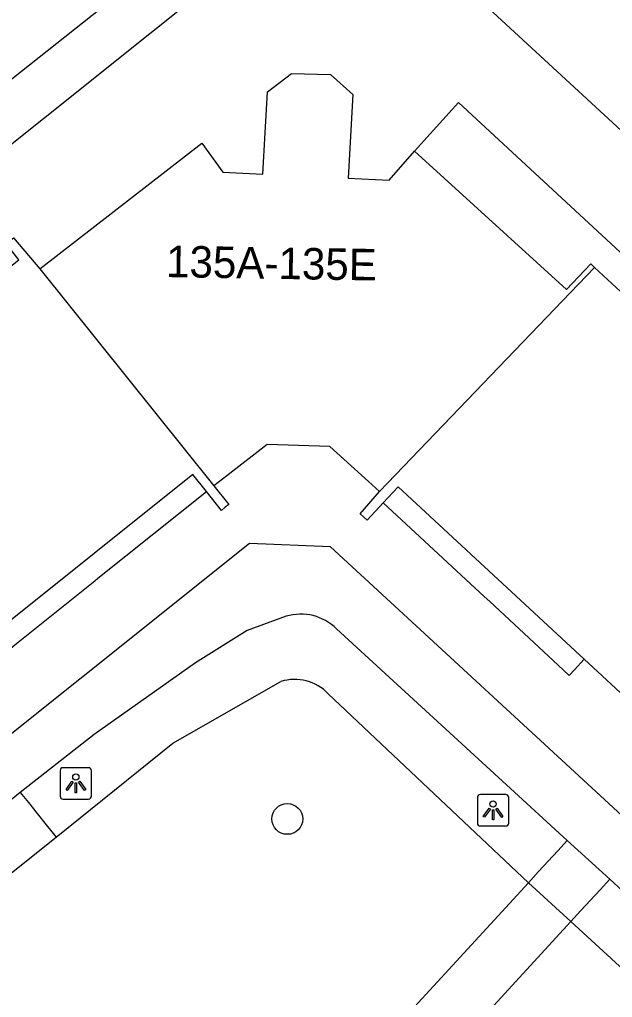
# Model space of a CAD drawing. Extents: x 159040 to 160094, y 381214 to 382518.
# Drawn here: x 159665.82 to 159684.64, y 381789.2 to 381820.24 of the extents above; entities that cross this region are included whole.
import ezdxf

# ---------------------------------------------------------------- set-up
doc = ezdxf.new("R2010")
doc.units = 0
for name, color, linetype in [('IMGEO_Boom', 7, 'Continuous'), ('IMGEO_Haag', 7, 'Continuous'), ('IMGEO_Lichtpunt', 7, 'Continuous'), ('IMGEO_Pand', 7, 'Continuous'), ('IMGEO_Pand_nummerreeks', 7, 'Continuous'), ('IMGEO_Pand_overbouw', 7, 'Continuous'), ('IMGEO_Rijbaan_lokaal_open', 7, 'Continuous'), ('IMGEO_Voetpad_gesloten', 7, 'Continuous'), ('IMGEO_Voetpad_open', 7, 'Continuous')]:
    doc.layers.add(name, color=color, linetype=linetype)

msp = doc.modelspace()

# ---------------------------------------------------------------- linework, layer by layer
at = {"layer": 'IMGEO_Boom'}
msp.add_circle((159674.317, 381794.866), 0.489, dxfattribs=at)
at = {"layer": 'IMGEO_Haag'}
for points in [[(159672.049, 381823.487), (159655.728, 381810.546)], [(159666.977, 381794.289), (159670.685, 381797.275), (159674.114, 381799.226)], [(159675.617, 381798.839), (159681.97, 381792.84)], [(159683.317, 381791.605), (159691.286, 381784.296)]]:
    msp.add_lwpolyline(points, dxfattribs=at)
msp.add_arc((159674.554, 381797.824), 1.47, 43.6887, 107.433, dxfattribs=at)
at = {"layer": 'IMGEO_Lichtpunt'}
for p, q in [((159667.108, 381796.396), (159667.108, 381795.589)), ((159667.108, 381796.396), (159667.108, 381795.589)), ((159668.01, 381796.491), (159667.202, 381796.491)), ((159668.01, 381796.491), (159667.202, 381796.491)), ((159668.104, 381795.589), (159668.104, 381796.396)), ((159668.104, 381795.589), (159668.104, 381796.396)), ((159667.202, 381795.495), (159668.01, 381795.495)), ((159667.202, 381795.495), (159668.01, 381795.495)), ((159680.351, 381795.543), (159680.351, 381794.736)), ((159680.351, 381795.543), (159680.351, 381794.736)), ((159681.253, 381795.638), (159680.445, 381795.638)), ((159681.253, 381795.638), (159680.445, 381795.638)), ((159681.347, 381794.736), (159681.347, 381795.543)), ((159681.347, 381794.736), (159681.347, 381795.543)), ((159680.445, 381794.642), (159681.253, 381794.642)), ((159680.445, 381794.642), (159681.253, 381794.642))]:
    msp.add_line(p, q, dxfattribs=at)
for points in [[(159667.482, 381796.06), (159667.521, 381796.032), (159667.333, 381795.77), (159667.295, 381795.797), (159667.482, 381796.06)], [(159667.694, 381796.032), (159667.732, 381796.059), (159667.919, 381795.797), (159667.88, 381795.769), (159667.694, 381796.032)], [(159667.584, 381796.012), (159667.631, 381796.012), (159667.631, 381795.69), (159667.584, 381795.69), (159667.584, 381796.012)], [(159680.725, 381795.207), (159680.764, 381795.179), (159680.576, 381794.917), (159680.538, 381794.944), (159680.725, 381795.207)], [(159680.827, 381795.159), (159680.874, 381795.159), (159680.874, 381794.837), (159680.827, 381794.837), (159680.827, 381795.159)], [(159680.937, 381795.179), (159680.975, 381795.206), (159681.162, 381794.944), (159681.123, 381794.916), (159680.937, 381795.179)]]:
    msp.add_lwpolyline(points, dxfattribs=at)
for centre in [(159667.607, 381796.194), (159680.85, 381795.341)]:
    msp.add_circle(centre, 0.0994, dxfattribs=at)
for centre, start, end in [((159667.202, 381796.396), 90, 180), ((159667.202, 381796.396), 90, 180), ((159668.01, 381796.396), 0, 90), ((159668.01, 381796.396), 0, 90), ((159667.202, 381795.589), 180, 270), ((159667.202, 381795.589), 180, 270), ((159668.01, 381795.589), 270, 0), ((159668.01, 381795.589), 270, 360), ((159680.445, 381795.543), 90, 180), ((159680.445, 381795.543), 90, 180), ((159681.253, 381795.543), 0, 90), ((159681.253, 381795.543), 0, 90), ((159680.445, 381794.736), 180, 270), ((159680.445, 381794.736), 180, 270), ((159681.253, 381794.736), 270, 0), ((159681.253, 381794.736), 270, 360)]:
    msp.add_arc(centre, 0.0946, start, end, dxfattribs=at)
at = {"layer": 'IMGEO_Pand'}
for points in [[(159666.46, 381812.323), (159671.61, 381816.317), (159672.268, 381815.393), (159673.54, 381815.331), (159673.617, 381816.646), (159673.692, 381817.941), (159674.447, 381818.524), (159675.692, 381818.488), (159676.402, 381817.853), (159676.247, 381815.206), (159677.547, 381815.142), (159678.35, 381816.059)], [(159684.065, 381812.371), (159683.949, 381812.478), (159683.182, 381811.667), (159678.35, 381816.059)], [(159651.632, 381801.285), (159665.8, 381812.605), (159665.398, 381813.125), (159665.632, 381813.306), (159666.46, 381812.323)], [(159666.46, 381812.323), (159671.99, 381805.439)], [(159677.249, 381805.254), (159684.065, 381812.371)], [(159690.949, 381806.021), (159684.065, 381812.371)], [(159677.249, 381805.254), (159676.89, 381805.578), (159675.665, 381806.682), (159673.683, 381806.752), (159672.398, 381805.754), (159671.99, 381805.439)], [(159671.99, 381805.439), (159672.462, 381804.845), (159672.351, 381804.757), (159672.227, 381804.658), (159671.751, 381805.257), (159671.323, 381805.795), (159665.042, 381800.778), (159663.368, 381799.441), (159657.148, 381794.473), (159657.587, 381793.923), (159658.181, 381793.179), (159658.107, 381793.119)], [(159691.334, 381792.901), (159690.86, 381792.394), (159690.216, 381791.705), (159690.022, 381791.881), (159690.662, 381792.576), (159691.135, 381793.089), (159685.321, 381798.475), (159683.739, 381799.941), (159677.836, 381805.408), (159677.363, 381804.896), (159676.856, 381804.347), (159676.748, 381804.443), (159676.626, 381804.55), (159677.249, 381805.254)]]:
    msp.add_lwpolyline(points, dxfattribs=at)
at = {"layer": 'IMGEO_Pand_overbouw'}
for points in [[(159671.751, 381805.257), (159671.323, 381805.795), (159665.042, 381800.778), (159665.318, 381800.432), (159665.475, 381800.237), (159665.671, 381800.394), (159668.158, 381802.383), (159668.36, 381802.545)], [(159683.739, 381799.941), (159677.836, 381805.408), (159677.363, 381804.896), (159680.563, 381801.927), (159680.743, 381801.764), (159683.074, 381799.597), (159683.266, 381799.419), (159683.437, 381799.602)]]:
    msp.add_lwpolyline(points, close=True, dxfattribs=at)
at = {"layer": 'IMGEO_Rijbaan_lokaal_open'}
msp.add_lwpolyline([(159689.119, 381812.848), (159667.17, 381833.086)], dxfattribs=at)
at = {"layer": 'IMGEO_Voetpad_gesloten'}
for points in [[(159703.332, 381778.057), (159702.939, 381778.5), (159699.62, 381781.437), (159675.685, 381803.499), (159673.113, 381803.604), (159630.084, 381769.208)], [(159674.285, 381801.296), (159673.041, 381800.851), (159671.4, 381799.822), (159668.191, 381797.543), (159665.84, 381795.709)], [(159683.2, 381794.179), (159675.882, 381800.896)], [(159665.84, 381795.709), (159664.425, 381794.557)], [(159683.2, 381794.179), (159684.552, 381792.952)], [(159692.511, 381785.612), (159684.552, 381792.952)]]:
    msp.add_lwpolyline(points, dxfattribs=at)
msp.add_arc((159674.748, 381799.758), 1.607, 45.1184, 106.7584, dxfattribs=at)
at = {"layer": 'IMGEO_Voetpad_open'}
for points in [[(159672.049, 381823.487), (159673.225, 381822.404), (159656.759, 381809.248), (159655.728, 381810.546)], [(159678.35, 381816.059), (159679.755, 381817.601), (159691.568, 381806.669), (159690.949, 381806.021)], [(159665.84, 381795.709), (159666.099, 381795.386), (159666.38, 381795.035), (159666.661, 381794.683), (159666.977, 381794.289)], [(159665.563, 381793.152), (159666.977, 381794.289)], [(159681.97, 381792.84), (159682.293, 381793.193), (159682.598, 381793.524), (159682.902, 381793.855), (159683.2, 381794.179)], [(159684.552, 381792.952), (159684.246, 381792.618), (159683.942, 381792.286), (159683.637, 381791.954), (159683.317, 381791.605)], [(159675.338, 381785.62), (159681.97, 381792.84)], [(159683.317, 381791.605), (159681.97, 381792.84)], [(159676.666, 381784.352), (159683.317, 381791.605)]]:
    msp.add_lwpolyline(points, dxfattribs=at)

# ---------------------------------------------------------------- texts
at = {"layer": 'IMGEO_Pand_nummerreeks'}
msp.add_text('135A-135E', height=1, rotation=359.0613, dxfattribs=at).set_placement((159670.463, 381812.063))

doc.saveas('drawing.dxf')
